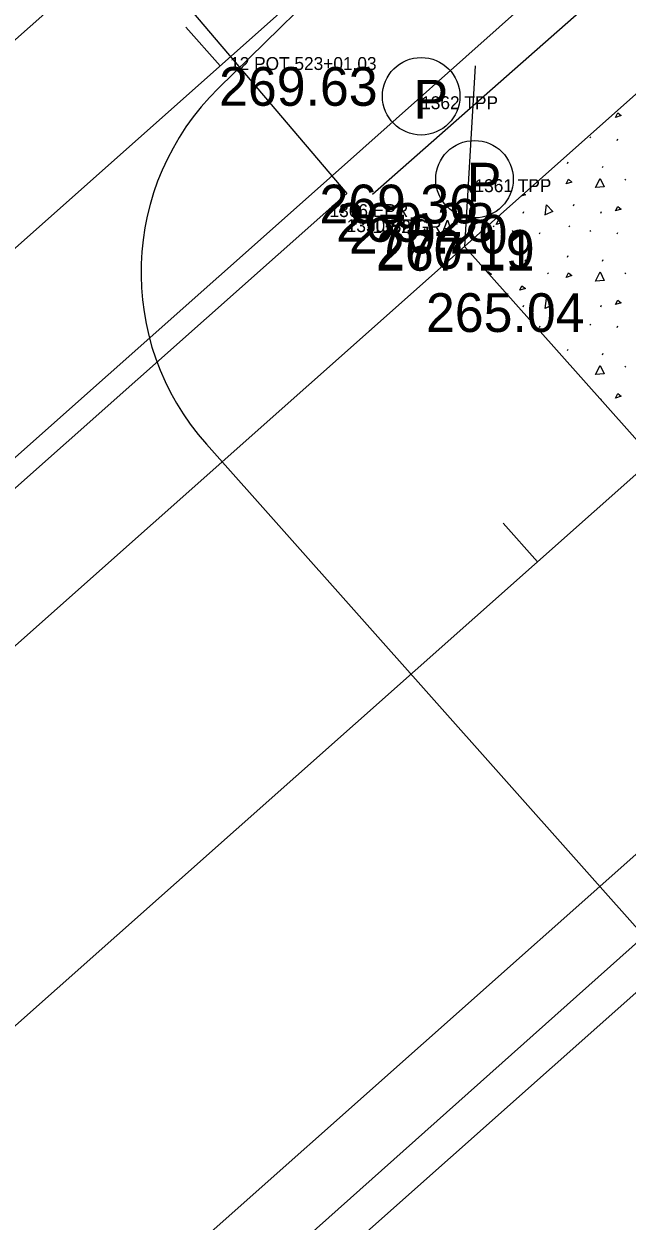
# Model space of a CAD drawing. Extents: x 49683 to 58852, y 49525 to 54803.
# Drawn here: x 53875.1 to 53921.8, y 51789.8 to 51882.5 of the extents above; entities that cross this region are included whole.
import ezdxf

# ---------------------------------------------------------------- set-up
doc = ezdxf.new("R2010")
doc.units = 0
for name, color, linetype in [('Level 1', 7, 'Continuous'), ('Level 11', 7, 'Continuous'), ('Level 13', 7, 'Continuous'), ('Level 15', 7, 'Continuous'), ('Level 18', 7, 'Continuous'), ('Level 19', 7, 'Continuous'), ('Level 3', 7, 'Continuous'), ('Level 32', 7, 'Continuous'), ('Level 5', 7, 'Continuous'), ('Level 51', 7, 'Continuous'), ('Level 53', 7, 'Continuous'), ('Level 55', 7, 'Continuous'), ('Level 57', 7, 'Continuous'), ('Level 59', 7, 'Continuous'), ('Level 7', 7, 'Continuous'), ('Level 9', 7, 'Continuous')]:
    doc.layers.add(name, color=color, linetype=linetype)

# ---------------------------------------------------------------- blocks, each defined once
blk = doc.blocks.new('TPP')
at = {"layer": 'Level 9'}
blk.add_circle((0, 0), 3, dxfattribs=at)
blk.add_text('P', height=3, dxfattribs=at).set_placement((-0.589, -1.729))

msp = doc.modelspace()

# ---------------------------------------------------------------- linework, layer by layer
at = {"layer": 'Level 1'}
for p, q in [((52544.807, 50683.302), (55534.583, 53340.862)), ((53890.278, 51879.268), (53887.621, 51882.257))]:
    msp.add_line(p, q, dxfattribs=at)
at = {"layer": 'Level 11'}
msp.add_line((53245.856, 51207.553), (53944.235, 51830.768), dxfattribs=at)
at = {"layer": 'Level 13'}
msp.add_line((53681.554, 51593.39), (53996.93, 51873.722), dxfattribs=at)
at = {"layer": 'Level 15'}
for p, q in [((53910.003, 51879.272), (53909.18, 51865.296)), ((53909.18, 51865.296), (53924.129, 51878.584)), ((53918.882, 51873.77), (53918.937, 51873.687)), ((53920.993, 51873.499), (53921.049, 51873.623)), ((53917.158, 51871.709), (53917.213, 51871.834)), ((53919.869, 51871.39), (53919.925, 51871.514)), ((53915.604, 51870.502), (53915.659, 51870.418)), ((53921.604, 51870.502), (53921.659, 51870.418)), ((53917.622, 51868.434), (53917.677, 51868.559)), ((53913.731, 51867.865), (53913.786, 51867.99)), ((53919.731, 51867.865), (53919.786, 51867.99)), ((53911.406, 51866.881), (53911.461, 51866.797)), ((53912.882, 51866.527), (53912.937, 51866.444)), ((53917.263, 51866.881), (53917.318, 51866.797)), ((53918.882, 51866.527), (53918.937, 51866.444)), ((53914.993, 51866.256), (53915.049, 51866.381)), ((53920.993, 51866.256), (53921.049, 51866.381)), ((53460.734, 51466.679), (53909.18, 51865.296)), ((53938.412, 51832.41), (53909.18, 51865.296)), ((53911.301, 51864.466), (53911.356, 51864.591)), ((53913.869, 51864.147), (53913.925, 51864.272)), ((53917.158, 51864.466), (53917.213, 51864.591)), ((53919.869, 51864.147), (53919.925, 51864.272)), ((53915.604, 51863.259), (53915.659, 51863.176)), ((53921.604, 51863.259), (53921.659, 51863.176)), ((53917.622, 51861.192), (53917.677, 51861.317)), ((53913.731, 51860.623), (53913.786, 51860.748)), ((53919.731, 51860.623), (53919.786, 51860.748)), ((53914.993, 51859.013), (53915.049, 51859.138)), ((53917.263, 51859.638), (53917.318, 51859.555)), ((53918.882, 51859.285), (53918.937, 51859.202)), ((53920.993, 51859.013), (53921.049, 51859.138)), ((53917.158, 51857.223), (53917.213, 51857.348)), ((53919.869, 51856.904), (53919.925, 51857.029)), ((53921.604, 51856.016), (53921.659, 51855.933)), ((53919.745, 51853.412), (53919.786, 51853.505)), ((53938.412, 51832.41), (53489.966, 51433.793))]:
    msp.add_line(p, q, dxfattribs=at)
for points in [[(53920.874, 51875.278), (53921.04, 51875.625), (53921.318, 51875.417), (53920.874, 51875.278)], [(53917.061, 51870.141), (53917.227, 51870.488), (53917.505, 51870.28), (53917.061, 51870.141)], [(53919.318, 51869.851), (53919.692, 51870.559), (53919.984, 51869.907), (53919.331, 51869.851)], [(53913.776, 51869.381), (53913.9, 51869.288), (53913.547, 51869.178)], [(53915.419, 51867.722), (53915.529, 51868.515), (53916.026, 51868.002), (53915.432, 51867.727)], [(53920.874, 51868.035), (53921.04, 51868.382), (53921.318, 51868.174), (53920.874, 51868.035)], [(53911.649, 51866.977), (53911.816, 51867.324), (53912.093, 51867.116), (53911.649, 51866.977)], [(53910.968, 51863.285), (53911, 51863.351), (53911.277, 51863.143), (53911.134, 51863.098)], [(53917.061, 51862.898), (53917.227, 51863.245), (53917.505, 51863.037), (53917.061, 51862.898)], [(53919.318, 51862.609), (53919.692, 51863.316), (53919.984, 51862.664), (53919.331, 51862.609)], [(53913.456, 51861.906), (53913.622, 51862.253), (53913.9, 51862.045), (53913.456, 51861.906)], [(53915.419, 51860.479), (53915.529, 51861.272), (53916.026, 51860.759), (53915.432, 51860.484)], [(53920.874, 51860.793), (53921.04, 51861.14), (53921.318, 51860.932), (53920.874, 51860.793)], [(53919.318, 51855.366), (53919.692, 51856.073), (53919.984, 51855.421), (53919.331, 51855.366)], [(53920.874, 51853.55), (53921.04, 51853.897), (53921.318, 51853.689), (53920.874, 51853.55)]]:
    msp.add_lwpolyline(points, dxfattribs=at)
at = {"layer": 'Level 18'}
for p, q in [((53890.152, 51877.545), (53921.658, 51908.457)), ((53889.211, 51849.982), (53927.094, 51807.363))]:
    msp.add_line(p, q, dxfattribs=at)
msp.add_arc((53904.159, 51863.269), 20, 134.45386, 221.63337, dxfattribs=at)
at = {"layer": 'Level 19'}
for p, q in [((52714.154, 50773.623), (54181.768, 52078.16)), ((53914.827, 51840.881), (53912.17, 51843.871))]:
    msp.add_line(p, q, dxfattribs=at)
at = {"layer": 'Level 3'}
for p, q in [((53898.742, 51870.567), (54083.389, 52035.124)), ((53434.092, 51489.844), (53883.273, 51889.178)), ((53449.718, 51471.806), (53898.742, 51870.567))]:
    msp.add_line(p, q, dxfattribs=at)
at = {"layer": 'Level 5'}
for p, q in [((53881.993, 51890.68), (53900.074, 51869.402)), ((53900.074, 51869.402), (53451.19, 51470.163))]:
    msp.add_line(p, q, dxfattribs=at)
at = {"layer": 'Level 7'}
msp.add_line((53902.065, 51869.327), (53922.854, 51887.665), dxfattribs=at)

# ---------------------------------------------------------------- block references
at = {"layer": 'Level 9'}
for p in [(53905.834, 51876.918), (53909.962, 51870.495)]:
    msp.add_blockref('TPP', p, dxfattribs=at)

# ---------------------------------------------------------------- texts
at = {"layer": 'Level 32'}
for s, p in [('269.63', (53890.195, 51876.179)), ('269.36', (53897.959, 51867.074)), ('269.28', (53899.247, 51865.651)), ('270.20', (53900.245, 51864.74)), ('270.19', (53902.346, 51863.565)), ('267.11', (53902.346, 51863.413)), ('265.04', (53906.204, 51858.669))]:
    msp.add_text(s, height=3, dxfattribs=at).set_placement(p)
at = {"layer": 'Level 51'}
msp.add_text('12 POT 523+01.03', height=1, dxfattribs=at).set_placement((53891.047, 51878.951))
at = {"layer": 'Level 53'}
msp.add_text('1366 EPR', height=1, dxfattribs=at).set_placement((53898.742, 51867.567))
at = {"layer": 'Level 55'}
msp.add_text('1350 BRC', height=1, dxfattribs=at).set_placement((53900.074, 51866.402))
at = {"layer": 'Level 57'}
msp.add_text('1352 GRA', height=1, dxfattribs=at).set_placement((53902.065, 51866.327))
at = {"layer": 'Level 59'}
for s, p in [('1362 TPP', (53905.834, 51875.918)), ('1361 TPP', (53909.962, 51869.495))]:
    msp.add_text(s, height=1, dxfattribs=at).set_placement(p)

doc.saveas('drawing.dxf')
